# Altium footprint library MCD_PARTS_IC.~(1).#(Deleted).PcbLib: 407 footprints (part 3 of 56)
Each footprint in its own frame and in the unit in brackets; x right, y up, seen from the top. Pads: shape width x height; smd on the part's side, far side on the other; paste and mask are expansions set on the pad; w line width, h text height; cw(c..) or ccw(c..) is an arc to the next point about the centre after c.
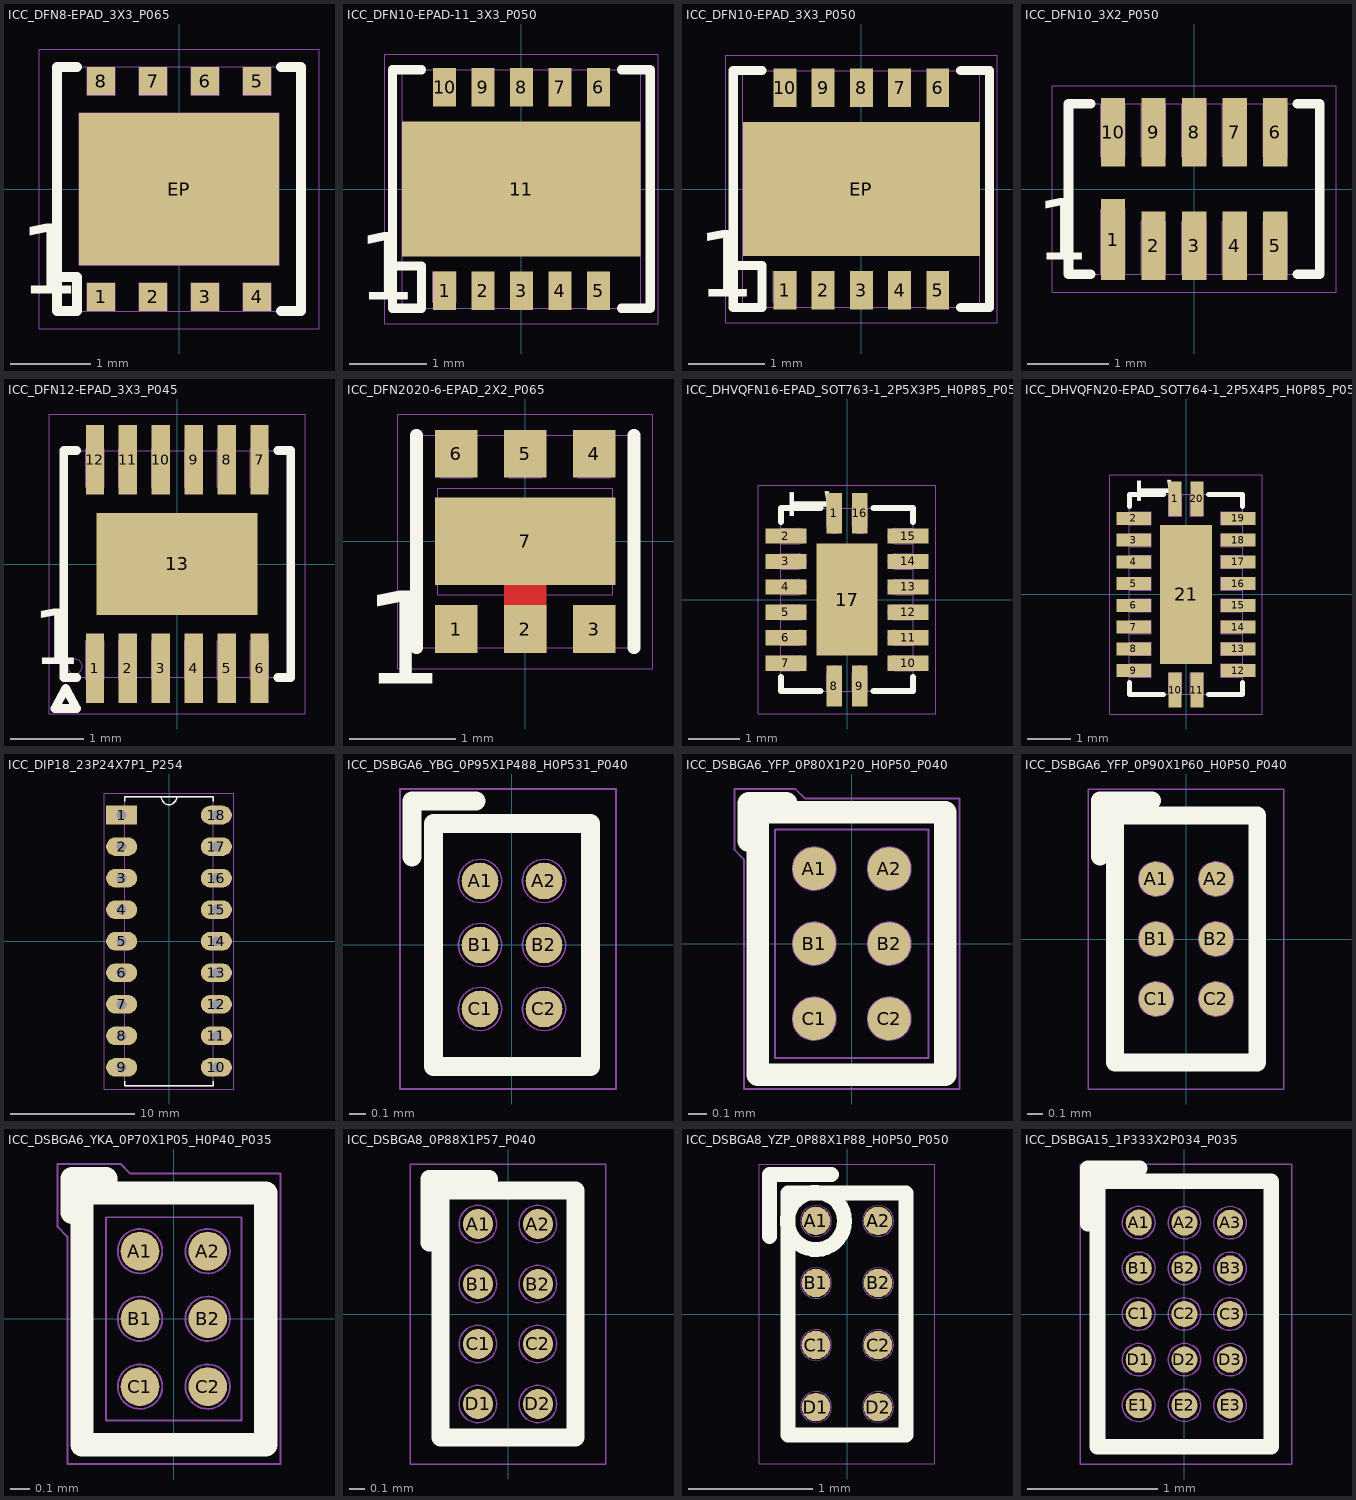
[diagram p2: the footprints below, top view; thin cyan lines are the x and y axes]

## ICC_DFN8-EPAD_3X3_P065 [mm]
height 0.9
pads (9):
  rect 0.35x0.35 smd mask+0.05: 1(-0.975,-1.35) 2(-0.325,-1.35) 3(0.325,-1.35) 4(0.975,-1.35) 5(0.975,1.35) 6(0.325,1.35) 7(-0.325,1.35) 8(-0.975,1.35)
  rect 2.5x1.9 smd mask+0.05: EP(0,0)
Top Overlay:
  lines w0.12: -1.525,-1.1 -1.275,-1.1 -1.275,-1.525 -1.525,-1.525 -1.525,1.525 -1.275,1.525 ; 1.275,-1.525 1.525,-1.525 1.525,1.525 1.275,1.525
  text "1" at -2,-1.6 h1.5
M14-Top Assembly:
  lines w0.01: -1.15,-1.525 -1.15,-1.175 -0.8,-1.175 -0.8,-1.525 ; -1.15,1.525 -1.15,1.175 -0.8,1.175 -0.8,1.525 ; -0.5,-1.525 -0.5,-1.175 -0.15,-1.175 -0.15,-1.525 ; -0.5,1.525 -0.5,1.175 -0.15,1.175 -0.15,1.525 ; 0.15,-1.525 0.15,-1.175 0.5,-1.175 0.5,-1.525 ; 0.15,1.525 0.15,1.175 0.5,1.175 0.5,1.525 ; 0.8,-1.525 0.8,-1.175 1.15,-1.175 1.15,-1.525 ; 0.8,1.525 0.8,1.175 1.15,1.175 1.15,1.525 ; -1.525,-1.525 1.525,-1.525 1.525,1.525 -1.525,1.525 -1.525,-1.525 ; -1.25,-0.95 1.25,-0.95 1.25,0.95 -1.25,0.95 -1.25,-0.95
  text "1" at -1.05,-1.525 h0.5
  text "4" at 0.85,-1.525 h0.5
  text "EP" at -0.25,-0.125 h0.5
  text "5" at 0.875,1.175 h0.5
  text "8" at -1.075,1.175 h0.5
  text "'.Designator'" at -2,0 h0.75
M16-Top Courtyard:
  lines w0.01: -1.75,-1.75 1.75,-1.75 1.75,1.75 -1.75,1.75 -1.75,-1.75
3D body: height 0.9, standoff 0, extent -1.525,-1.525 1.525,1.525
3D body "User Library-DFN8N_65.STEP": height 0.9, standoff 0, extent -1.49,-1.5 1.5,1.5

## ICC_DFN10-EPAD-11_3X3_P050 [mm]
height 1
pads (11):
  rect 0.3x0.5 smd mask+0.05: 1(-1,-1.325) 2(-0.5,-1.325) 3(0,-1.325) 4(0.5,-1.325) 5(1,-1.325) 6(1,1.325) 7(0.5,1.325) 8(0,1.325) 9(-0.5,1.325) 10(-1,1.325)
  rect 3.1x1.75 smd mask+0.05: 11(0,0)
Top Overlay:
  lines w0.12: -1.675,-1 -1.3,-1 -1.3,-1.55 -1.675,-1.55 -1.675,1.55 -1.3,1.55 ; 1.3,-1.55 1.675,-1.55 1.675,1.55 1.3,1.55
  text "1" at -2.125,-1.725 h1.5
M14-Top Assembly:
  lines w0.01: -1.55,-1.55 -1.55,1.55 1.55,1.55 1.55,-1.55 -1.55,-1.55 ; -1.15,-1.475 -0.85,-1.475 -0.85,-1.075 -1.15,-1.075 -1.15,-1.475
  text "'.Designator'" at -2,-0.5 h0.75
M16-Top Courtyard:
  lines w0.01: -1.775,-1.75 -1.775,1.75 1.775,1.75 1.775,-1.75 -1.775,-1.75
3D body "DFN-10-3x3-0_5.STEP": height 0.8, standoff 0, extent -1.55,-1.56 1.55,1.56
3D body: height 1, standoff 0, extent -1.55,-1.55 1.55,1.55

## ICC_DFN10-EPAD_3X3_P050 [mm]
height 1
pads (11):
  rect 0.3x0.5 smd mask+0.05: 1(-1,-1.325) 2(-0.5,-1.325) 3(0,-1.325) 4(0.5,-1.325) 5(1,-1.325) 6(1,1.325) 7(0.5,1.325) 8(0,1.325) 9(-0.5,1.325) 10(-1,1.325)
  rect 3.1x1.75 smd mask+0.05: EP(0,0)
Top Overlay:
  lines w0.12: -1.675,-1 -1.3,-1 -1.3,-1.55 -1.675,-1.55 -1.675,1.55 -1.3,1.55 ; 1.3,-1.55 1.675,-1.55 1.675,1.55 1.3,1.55
  text "1" at -2.15,-1.7 h1.5
M14-Top Assembly:
  lines w0.01: -1.55,-1.55 -1.55,1.55 1.55,1.55 1.55,-1.55 -1.55,-1.55 ; -1.15,-1.475 -0.85,-1.475 -0.85,-1.075 -1.15,-1.075 -1.15,-1.475
  text "'.Designator'" at -2,-0.5 h0.75
M16-Top Courtyard:
  lines w0.01: -1.775,-1.75 -1.775,1.75 1.775,1.75 1.775,-1.75 -1.775,-1.75
3D body "DFN-10-3x3-0_5.STEP": height 0.8, standoff 0, extent -1.55,-1.56 1.55,1.56
3D body: height 1, standoff 0, extent -1.55,-1.55 1.55,1.55

## ICC_DFN10_3X2_P050 [mm] "MCD-01488"
height 0.6
pads (10):
  rect 0.3x1 smd mask+0.05: 1(-1,-0.625)
  rect 0.3x0.85 smd mask+0.05: 2(-0.5,-0.7) 3(0,-0.7) 4(0.5,-0.7) 5(1,-0.7) 6(1,0.7) 7(0.5,0.7) 8(0,0.7) 9(-0.5,0.7) 10(-1,0.7)
Top Overlay:
  lines w0.12: -1.275,-1.05 -1.55,-1.05 -1.55,1.05 -1.275,1.05 ; 1.275,-1.05 1.55,-1.05 1.55,1.05 1.275,1.05
  text "1" at -1.95,-1.125 h1.3
M14-Top Assembly:
  lines w0.01: -1.15,-1.05 -1.15,-0.25 -0.85,-0.25 -0.85,-1.05 ; -1.15,1.05 -1.15,0.4 -0.85,0.4 -0.85,1.05 ; -0.65,-1.05 -0.65,-0.4 -0.35,-0.4 -0.35,-1.05 ; -0.65,1.05 -0.65,0.4 -0.35,0.4 -0.35,1.05 ; -0.15,-1.05 -0.15,-0.4 0.15,-0.4 0.15,-1.05 ; -0.15,1.05 -0.15,0.4 0.15,0.4 0.15,1.05 ; 0.35,-1.05 0.35,-0.4 0.65,-0.4 0.65,-1.05 ; 0.35,1.05 0.35,0.4 0.65,0.4 0.65,1.05 ; 0.85,-1.05 0.85,-0.4 1.15,-0.4 1.15,-1.05 ; 0.85,1.05 0.85,0.4 1.15,0.4 1.15,1.05 ; -1.55,-1.05 1.55,-1.05 1.55,1.05 -1.55,1.05 -1.55,-1.05
  text "10" at -1.3,0.55 h0.7
  text "6" at 0.85,0.55 h0.7
  text "5" at 0.85,-1 h0.7
  text "1" at -1.1,-1 h0.85
  text "'.Designator'" at -2,-0.5 h0.75
M16-Top Courtyard:
  lines w0.01: -1.75,-1.275 1.75,-1.275 1.75,1.275 -1.225,1.275 -1.75,1.275 -1.75,-1.25 -1.75,-1.275
3D body: height 0.6, standoff 0, extent -1.55,-1.05 1.55,1.05
3D body: height 0.61, standoff 0.6, extent -1.5,-1 -1.125,-0.625

## ICC_DFN12-EPAD_3X3_P045 [mm] "MCD-01952"
height 0.8
pads (13):
  rect 0.25x0.95 smd mask+0.05: 1(-1.125,-1.425) 2(-0.675,-1.425) 3(-0.225,-1.425) 4(0.225,-1.425) 5(0.675,-1.425) 6(1.125,-1.425) 7(1.125,1.425) 8(0.675,1.425) 9(0.225,1.425) 10(-0.225,1.425) 11(-0.675,1.425) 12(-1.125,1.425)
  rect 2.2x1.4 smd mask+0.05: 13(0,0)
Top Overlay:
  lines w0.12: -1.375,-1.55 -1.55,-1.55 ; 1.375,1.55 1.55,1.55 ; -1.55,-1.55 -1.55,1.55 -1.375,1.55 ; -1.55,-1.55 -1.55,-1.55 ; -1.375,1.55 -1.375,1.55 ; 1.375,-1.55 1.55,-1.55 1.55,1.55 ; 1.375,-1.55 1.375,-1.55 ; 1.55,1.55 1.55,1.55 ; -1.675,-1.975 -1.375,-1.975 -1.525,-1.7 -1.675,-1.975
  text "1" at -1.975,-1.625 h1.3
M14-Top Assembly:
  circle w0.01: c-1.4,-1.4 r0.1
  lines w0.01: -1.25,1.55 -1.25,1.575 ; -1,-1.55 -1,-1.575 ; -0.8,1.55 -0.8,1.575 ; -0.55,-1.55 -0.55,-1.575 ; -0.35,1.55 -0.35,1.575 ; -0.1,-1.55 -0.1,-1.575 ; 0.1,1.55 0.1,1.575 ; 0.35,-1.55 0.35,-1.575 ; 0.55,1.55 0.55,1.575 ; 0.8,-1.55 0.8,-1.575 ; 1,1.55 1,1.575 ; 1.25,-1.55 1.25,-1.575 ; -1.25,1.575 -1.25,1.05 -1,1.05 -1,1.55 -1,1.575 -1.25,1.575 ; -1.05,-0.45 -0.85,-0.65 1.05,-0.65 1.05,0.65 -1.05,0.65 -1.05,-0.45 ; -1.05,-0.45 -1.05,-0.45 ; -1,-1.575 -1.25,-1.575 -1.25,-1.55 -1.25,-1.05 -1,-1.05 -1,-1.575 ; -0.8,1.575 -0.55,1.575 -0.55,1.55 -0.55,1.05 -0.8,1.05 -0.8,1.575 ; -0.55,-1.575 -0.8,-1.575 -0.8,-1.55 -0.8,-1.05 -0.55,-1.05 -0.55,-1.575 ; -0.35,1.575 -0.1,1.575 -0.1,1.55 -0.1,1.05 -0.35,1.05 -0.35,1.575 ; -0.1,-1.575 -0.35,-1.575 -0.35,-1.55 -0.35,-1.05 -0.1,-1.05 -0.1,-1.575 ; 0.1,1.575 0.35,1.575 0.35,1.55 0.35,1.05 0.1,1.05 0.1,1.575 ; 0.35,-1.575 0.1,-1.575 0.1,-1.55 0.1,-1.05 0.35,-1.05 0.35,-1.575 ; 0.55,1.575 0.8,1.575 0.8,1.55 0.8,1.05 0.55,1.05 0.55,1.575 ; 0.8,-1.575 0.55,-1.575 0.55,-1.55 0.55,-1.05 0.8,-1.05 0.8,-1.575 ; 1,1.575 1.25,1.575 1.25,1.55 1.25,1.05 1,1.05 1,1.575 ; 1.25,-1.575 1,-1.575 1,-1.55 1,-1.05 1.25,-1.05 1.25,-1.575 ; -1.55,-1.55 1.55,-1.55 1.55,1.55 -1.55,1.55 -1.55,-1.55
  text "12" at -1.4,1.1 h0.6
  text "7" at 1,1.125 h0.6
  text "6" at 1,-1.5 h0.6
  text "1" at -1.2,-1.5 h0.6
  text "'.Designator'" at -2,0.125 h0.75
  text "13" at -0.275,-0.175 h0.6
M16-Top Courtyard:
  lines w0.01: -1.75,-2.05 1.75,-2.05 1.75,2.05 -1.75,2.05 -1.75,-2.05
3D body: height 0.8, standoff 0, extent -1.55,-1.55 1.55,1.55
3D body "DFN12(3x3)-1.STEP": height 0.76, standoff 0, extent -1.5,-1.501 1.5,1.501

## ICC_DFN2020-6-EPAD_2X2_P065 [mm] "MCD-012963"
height 0.65
pads (7):
  rect 0.4x0.45 smd mask+0.05: 1(-0.65,-0.825) 2(0,-0.825) 3(0.65,-0.825) 4(0.65,0.825) 5(0,0.825) 6(-0.65,0.825)
  rect 1.7x0.825 smd mask+0.05: 7(0,0)
Top Layer:
  region: -0.2,0.2 0.2,0.2 0.2,-1.05 -0.2,-1.05
Top Overlay:
  lines w0.12: -1.025,-1 -1.025,1 ; 1.025,-1 1.025,1
  text "1" at -1.525,-1.625 h1.5
M14-Top Assembly:
  lines w0.01: -0.8,-1 -0.8,-0.6 -0.5,-0.6 -0.5,-1 ; -0.8,1 -0.8,0.6 -0.5,0.6 -0.5,1 ; -0.15,-1 -0.15,-0.5 -0.825,-0.5 -0.825,0.5 0.825,0.5 0.825,-0.5 0.15,-0.5 0.15,-1 ; -0.15,1 -0.15,0.6 0.15,0.6 0.15,1 0.175,1 ; 0.475,1 0.5,1 0.5,0.6 0.8,0.6 0.8,1 0.825,1 ; 0.5,-1 0.5,-0.6 0.8,-0.6 0.8,-1 ; -1,-1 1,-1 1,1 -1,1 -1,-1
  text "'.Designator'" at 0,0 h0.75
  text "1" at -0.7,-0.975 h0.4
  text "2" at -0.075,-0.975 h0.4
  text "3" at 0.575,-0.975 h0.4
  text "4" at 0.55,0.725 h0.4
  text "5" at -0.075,0.725 h0.4
  text "6" at -0.725,0.725 h0.4
  text "7" at -0.075,-0.15 h0.4
M16-Top Courtyard:
  lines w0.01: -1.2,-1.2 -1.2,1.2 1.2,1.2 1.2,-1.2 -1.2,-1.2
3D body: height 1.01, standoff 1, extent -0.899,-0.9 -0.6,-0.6
3D body: height 0.6, standoff 0, extent -1,-1 1,1

## ICC_DHVQFN16-EPAD_SOT763-1_2P5X3P5_H0P85_P050 [mm] "MCD-01945"
height 1
pads (17):
  rect 0.3x0.8 smd mask+0.05: 1(-0.25,1.7) 8(-0.25,-1.7) 9(0.25,-1.7) 16(0.25,1.7)
  rect 0.8x0.3 smd mask+0.05: 2(-1.2,1.25) 3(-1.2,0.75) 4(-1.2,0.25) 5(-1.2,-0.25) 6(-1.2,-0.75) 7(-1.2,-1.25) 10(1.2,-1.25) 11(1.2,-0.75) 12(1.2,-0.25) 13(1.2,0.25) 14(1.2,0.75) 15(1.2,1.25)
  rect 1.2x2.2 smd mask+0.05: 17(0,0)
Top Overlay:
  lines w0.12: -1.3,-1.525 -1.3,-1.8 -0.525,-1.8 ; -1.3,1.525 -1.3,1.8 -0.525,1.8 ; 0.525,-1.8 1.3,-1.8 1.3,-1.525 ; 0.525,1.8 1.3,1.8 1.3,1.525
  text "1" at -1.4,2.25 h1.4
M14-Top Assembly:
  lines w0.01: -1.3,-1.4 -0.95,-1.4 ccw(c-0.95,-1.25) -0.8,-1.25 ccw(c-0.95,-1.25) -0.95,-1.1 -1.3,-1.1 ; -1.3,-0.9 -0.95,-0.9 ccw(c-0.95,-0.75) -0.8,-0.75 ccw(c-0.95,-0.75) -0.95,-0.6 -1.3,-0.6 ; -1.3,-0.4 -0.95,-0.4 ccw(c-0.95,-0.25) -0.8,-0.25 ccw(c-0.95,-0.25) -0.95,-0.1 -1.3,-0.1 ; -1.3,0.1 -0.95,0.1 ccw(c-0.95,0.25) -0.8,0.25 ccw(c-0.95,0.25) -0.95,0.4 -1.3,0.4 ; -1.3,0.6 -0.95,0.6 ccw(c-0.95,0.75) -0.8,0.75 ccw(c-0.95,0.75) -0.95,0.9 -1.3,0.9 ; -1.3,1.1 -0.95,1.1 ccw(c-0.95,1.25) -0.8,1.25 ccw(c-0.95,1.25) -0.95,1.4 -1.3,1.4 ; -0.4,-1.8 -0.4,-1.45 cw(c-0.25,-1.45) -0.25,-1.3 cw(c-0.25,-1.45) -0.1,-1.45 -0.1,-1.8 ; -0.4,1.8 -0.4,1.45 ccw(c-0.25,1.45) -0.25,1.3 ccw(c-0.25,1.45) -0.1,1.45 -0.1,1.8 ; 0.1,-1.8 0.1,-1.45 cw(c0.25,-1.45) 0.25,-1.3 cw(c0.25,-1.45) 0.4,-1.45 0.4,-1.8 ; 0.1,1.8 0.1,1.45 ccw(c0.25,1.45) 0.25,1.3 ccw(c0.25,1.45) 0.4,1.45 0.4,1.8 ; 1.3,-1.4 0.95,-1.4 cw(c0.95,-1.25) 0.8,-1.25 cw(c0.95,-1.25) 0.95,-1.1 1.3,-1.1 ; 1.3,-0.9 0.95,-0.9 cw(c0.95,-0.75) 0.8,-0.75 cw(c0.95,-0.75) 0.95,-0.6 1.3,-0.6 ; 1.3,-0.4 0.95,-0.4 cw(c0.95,-0.25) 0.8,-0.25 cw(c0.95,-0.25) 0.95,-0.1 1.3,-0.1 ; 1.3,0.1 0.95,0.1 cw(c0.95,0.25) 0.8,0.25 cw(c0.95,0.25) 0.95,0.4 1.3,0.4 ; 1.3,0.6 0.95,0.6 cw(c0.95,0.75) 0.8,0.75 cw(c0.95,0.75) 0.95,0.9 1.3,0.9 ; 1.3,1.1 0.95,1.1 cw(c0.95,1.25) 0.8,1.25 cw(c0.95,1.25) 0.95,1.4 1.3,1.4 ; -1.3,-1.8 1.3,-1.8 1.3,1.8 -1.3,1.8 -1.3,-1.8 ; -0.575,-1.075 0.575,-1.075 0.575,1.075 -0.575,1.075 -0.575,-1.075
  text "17" at -0.175,-0.125 h0.4
  text "16" at 0.425,1.7 h0.4
  text "2" at -1.175,1.325 h0.4
  text "7" at -1.2,-1.175 h0.4
  text "8" at -0.325,-1.675 h0.4
  text "9" at 0.175,-1.675 h0.4
  text "10" at 1.225,-1.425 h0.4
  text "15" at 1.225,1.075 h0.4
  text "'.Designator'" at -2,-0.5 h0.75
  text "1" at -0.2,1.7 h0.4
M16-Top Courtyard:
  lines w0.01: -1.75,-2.25 1.75,-2.25 1.75,2.25 -1.75,2.25 -1.75,-2.25
3D body "User Library-User Library-DHVQFN 16-1.STEP": height 1, standoff -0.05, extent -1.31,-1.81 1.31,1.81
3D body: height 1, standoff 0, extent -1.3,-1.81 1.3,1.81
3D body: height 1.01, standoff 1, extent -0.624,1.326 -0.226,1.725

## ICC_DHVQFN20-EPAD_SOT764-1_2P5X4P5_H0P85_P050 [mm] "MCD-01620"
height 1
pads (21):
  rect 0.3x0.8 smd mask+0.05: 1(-0.25,2.2) 10(-0.25,-2.2) 11(0.25,-2.2) 20(0.25,2.2)
  rect 0.8x0.3 smd mask+0.05: 2(-1.2,1.75) 3(-1.2,1.25) 4(-1.2,0.75) 5(-1.2,0.25) 6(-1.2,-0.25) 7(-1.2,-0.75) 8(-1.2,-1.25) 9(-1.2,-1.75) 12(1.2,-1.75) 13(1.2,-1.25) 14(1.2,-0.75) 15(1.2,-0.25) 16(1.2,0.25) 17(1.2,0.75) 18(1.2,1.25) 19(1.2,1.75)
  rect 1.2x3.2 smd mask+0.05: 21(0,0)
Top Overlay:
  lines w0.12: -1.3,-2.025 -1.3,-2.3 -0.525,-2.3 ; -1.3,2.025 -1.3,2.3 -0.525,2.3 ; 0.525,-2.3 1.3,-2.3 1.3,-2.025 ; 0.525,2.3 1.3,2.3 1.3,2.025
  text "1" at -1.4,2.75 h1.4
M14-Top Assembly:
  lines w0.01: -1.3,-1.9 -0.8,-1.9 -0.8,-1.6 -1.3,-1.6 ; -1.3,-1.4 -0.8,-1.4 -0.8,-1.1 -1.3,-1.1 ; -1.3,-0.9 -0.8,-0.9 -0.8,-0.6 -1.3,-0.6 ; -1.3,-0.4 -0.8,-0.4 -0.8,-0.1 -1.3,-0.1 ; -1.3,0.1 -0.8,0.1 -0.8,0.4 -1.3,0.4 ; -1.3,0.6 -0.8,0.6 -0.8,0.9 -1.3,0.9 ; -1.3,1.1 -0.8,1.1 -0.8,1.4 -1.3,1.4 ; -1.3,1.6 -0.8,1.6 -0.8,1.9 -1.3,1.9 ; -0.4,-2.3 -0.4,-1.8 -0.1,-1.8 -0.1,-2.3 ; -0.4,2.3 -0.4,1.8 -0.1,1.8 -0.1,2.3 ; 0.1,-2.3 0.1,-1.8 0.4,-1.8 0.4,-2.3 ; 0.1,2.3 0.1,1.8 0.4,1.8 0.4,2.3 ; 1.3,-1.9 0.8,-1.9 0.8,-1.6 1.3,-1.6 ; 1.3,-1.4 0.8,-1.4 0.8,-1.1 1.3,-1.1 ; 1.3,-0.9 0.8,-0.9 0.8,-0.6 1.3,-0.6 ; 1.3,-0.4 0.8,-0.4 0.8,-0.1 1.3,-0.1 ; 1.3,0.1 0.8,0.1 0.8,0.4 1.3,0.4 ; 1.3,0.6 0.8,0.6 0.8,0.9 1.3,0.9 ; 1.3,1.1 0.8,1.1 0.8,1.4 1.3,1.4 ; 1.3,1.6 0.8,1.6 0.8,1.9 1.3,1.9 ; -1.3,-2.3 1.3,-2.3 1.3,2.3 -1.3,2.3 -1.3,-2.3 ; -0.575,-1.575 0.575,-1.575 0.575,1.575 -0.575,1.575 -0.575,-1.575
  text "1" at -0.3,1.95 h0.35
  text "'.Designator'" at -2,0.3 h0.75
  text "20" at 0.1,1.95 h0.35
  text "2" at -1.1,1.65 h0.35
  text "9" at -1.1,-1.875 h0.35
  text "10" at -0.4,-2.175 h0.35
  text "11" at 0.125,-2.175 h0.35
  text "21" at -0.15,-0.125 h0.35
  text "12" at 0.9,-1.875 h0.35
  text "19" at 0.9,1.65 h0.35
M16-Top Courtyard:
  lines w0.01: -1.75,-2.75 -1.75,2.75 -1.3,2.75 1.75,2.75 1.75,2.55 1.75,-2.75 -0.4,-2.75 -1.75,-2.75
3D body "DHVQFN20.STEP": height 1, standoff 0, extent -1.26,-2.26 1.26,2.26
3D body: height 1, standoff 0, extent -1.3,-2.3 1.3,2.3
3D body: height 1.01, standoff 1, extent -0.648,1.8 -0.25,2.2
3D body: height 1.01, standoff 1, extent -0.648,1.801 -0.25,2.2

## ICC_DIP18_23P24X7P1_P254 [mm] "MCD-03104"
height 3.93
pads (18):
  rect 2.5x1.5 hole 0.8 mask+0.05: 1(-3.81,10.16)
  oval 2.5x1.5 hole 0.8 mask+0.05: 2(-3.81,7.62) 3(-3.81,5.08) 4(-3.81,2.54) 5(-3.81,0) 6(-3.81,-2.54) 7(-3.81,-5.08) 8(-3.81,-7.62) 9(-3.81,-10.16) 10(3.81,-10.16) 11(3.81,-7.62) 12(3.81,-5.08) 13(3.81,-2.54) 14(3.81,0) 15(3.81,2.54) 16(3.81,5.08) 17(3.81,7.62) 18(3.81,10.16)
Top Overlay:
  lines w0.12: -3.55,-11.261 -3.55,-11.62 3.55,-11.62 3.55,-11.261 ; -3.55,11.261 -3.55,11.62 3.55,11.62 3.55,11.261 ; -0.624,11.62 ccw(c-0.004,11.62) -0.004,11 ccw(c-0.004,11.629) 0.625,11.62
M14-Top Assembly:
  lines w0.01: -0.624,11.62 ccw(c-0.004,11.62) -0.004,11 ccw(c-0.004,11.629) 0.625,11.62 ; -3.55,-11.62 3.55,-11.62 3.55,11.62 -3.55,11.62 -3.55,-11.62
  text "1" at -3.925,9.9 h1
  text "'.Designator'" at -2,-0.5 h0.75
M16-Top Courtyard:
  lines w0.01: -5.2,-11.9 5.2,-11.9 5.2,11.9 -5.2,11.9 -5.2,-11.9
3D body "User Library-DIP-18P-M02.STEP": height 5, standoff -3, extent -3.945,-11 3.925,11

## ICC_DSBGA6_YBG_0P95X1P488_H0P531_P040 [mm] "MCD-04417"
height 0.531
pads (6):
  round 0.23 smd paste+0 mask+0.05: A1(-0.2,0.4) A2(0.2,0.4) B1(-0.2,0) B2(0.2,0) C1(-0.2,-0.4) C2(0.2,-0.4)
Top Overlay:
  lines w0.12: -0.625,0.55 -0.625,0.9 -0.225,0.9 ; -0.49,-0.759 -0.49,0.759 0.49,0.759 0.49,-0.759 -0.49,-0.759
Top Paste:
  drawing of 6 lines, arcs and shapes, not listed
M14-Top Assembly:
  circle w0.01: c-0.2,0.4 r0.135
  circle w0.01: c0.2,0.4 r0.135
  circle w0.01: c-0.2,0 r0.135
  circle w0.01: c0.2,0 r0.135
  circle w0.01: c0.2,-0.4 r0.135
  circle w0.01: c-0.2,-0.4 r0.135
  lines w0.01: -0.475,0.759 -0.49,0.759 ; -0.49,0.759 0.49,0.759 0.49,-0.759 -0.49,-0.759 -0.49,0.759
  text "A1" at -0.317,0.323 h0.25
  text "A2" at 0.069,0.323 h0.25
  text "B1" at -0.308,-0.077 h0.25
  text "B2" at 0.077,-0.077 h0.25
  text "C1" at -0.317,-0.479 h0.25
  text "C2" at 0.068,-0.479 h0.25
  text ".Designator" at -2.252,-0.226 h1
M16-Top Courtyard:
  lines w0.01: -0.7,-0.9 0.65,-0.9 0.65,0.975 -0.7,0.975 -0.7,-0.9
3D body: height 0.27, standoff 0, extent 0.061,-0.535 0.331,-0.265
3D body: height 0.27, standoff 0, extent -0.339,-0.535 -0.069,-0.265
3D body: height 0.27, standoff 0, extent 0.061,-0.135 0.331,0.135
3D body: height 0.27, standoff 0, extent -0.339,-0.135 -0.069,0.135
3D body: height 0.27, standoff 0, extent 0.061,0.265 0.331,0.535
3D body: height 0.27, standoff 0, extent -0.339,0.265 -0.069,0.535
3D body: height 0.53, standoff 0.53, extent -0.49,0.449 -0.28,0.759
3D body: height 0.53, standoff 0.16, extent -0.49,-0.759 0.49,0.759

## ICC_DSBGA6_YFP_0P80X1P20_H0P50_P040 [mm] "MCD-02469"
height 0.5
pads (6):
  round 0.23 smd paste+0 mask+0.05: A1(-0.2,0.4) A2(0.2,0.4) B1(-0.2,0) B2(0.2,0) C1(-0.2,-0.4) C2(0.2,-0.4)
Top Overlay:
  lines w0.12: -0.55,0.55 -0.55,0.75 -0.35,0.75 ; -0.35,0.7 -0.5,0.7 ; -0.5,0.7 0.5,0.7 0.5,-0.7 -0.5,-0.7 -0.5,0.7
Top Paste:
  drawing of 6 lines, arcs and shapes, not listed
M14-Top Assembly:
  circle w0.01: c-0.2,0.4 r0.115
  circle w0.01: c0.2,0.4 r0.115
  circle w0.01: c-0.2,0 r0.115
  circle w0.01: c0.2,0 r0.115
  circle w0.01: c0.2,-0.4 r0.115
  circle w0.01: c-0.2,-0.4 r0.115
  lines w0.01: -0.41,-0.61 0.41,-0.61 0.41,0.61 -0.41,0.61 -0.41,-0.61
  text "'.Designator'" at -2,-0.5 h0.75
  text "A1" at -0.317,0.323 h0.25
  text "A2" at 0.069,0.323 h0.25
  text "B1" at -0.308,-0.077 h0.25
  text "B2" at 0.077,-0.077 h0.25
  text "C1" at -0.317,-0.479 h0.25
  text "C2" at 0.068,-0.479 h0.25
M16-Top Courtyard:
  lines w0.01: -0.625,0.5 -0.625,0.825 -0.3,0.825 -0.25,0.775 0.575,0.775 0.575,-0.775 -0.575,-0.775 -0.575,0.45 -0.625,0.5
3D body: height 0.5, standoff 0.16, extent -0.41,-0.61 0.41,0.61
3D body: height 0.24, standoff -0.02, extent 0.074,-0.528 0.326,-0.272
3D body: height 0.24, standoff -0.02, extent -0.326,-0.528 -0.074,-0.272
3D body: height 0.24, standoff -0.02, extent 0.074,-0.128 0.326,0.128
3D body: height 0.24, standoff -0.02, extent -0.326,-0.128 -0.074,0.128
3D body: height 0.24, standoff -0.02, extent 0.074,0.272 0.326,0.528
3D body: height 0.24, standoff -0.02, extent -0.326,0.272 -0.074,0.528
3D body: height 0.51, standoff 0.5, extent -0.41,0.3 -0.2,0.61

## ICC_DSBGA6_YFP_0P90X1P60_H0P50_P040 [mm] "MCD-03759"
height 0.5
pads (6):
  round 0.23 smd paste+0 mask+0.05: A1(-0.2,0.4) A2(0.2,0.4) B1(-0.2,0) B2(0.2,0) C1(-0.2,-0.4) C2(0.2,-0.4)
Top Overlay:
  lines w0.12: -0.575,0.55 -0.575,0.925 -0.225,0.925 ; -0.475,-0.825 0.475,-0.825 0.475,0.825 -0.475,0.825 -0.475,-0.825
Top Paste:
  drawing of 6 lines, arcs and shapes, not listed
M14-Top Assembly:
  circle w0.01: c-0.2,-0.4 r0.115
  circle w0.01: c0.2,-0.4 r0.115
  circle w0.01: c0.2,0 r0.115
  circle w0.01: c-0.2,0 r0.115
  circle w0.01: c0.2,0.4 r0.115
  circle w0.01: c-0.2,0.4 r0.115
  lines w0.01: -0.45,-0.8 0.45,-0.8 0.45,0.8 -0.45,0.8 -0.45,-0.8
  text ".Designator" at -2.252,-0.226 h1
  text "C2" at 0.068,-0.479 h0.25
  text "C1" at -0.317,-0.479 h0.25
  text "B2" at 0.077,-0.077 h0.25
  text "B1" at -0.308,-0.077 h0.25
  text "A2" at 0.069,0.323 h0.25
  text "A1" at -0.317,0.323 h0.25
M16-Top Courtyard:
  lines w0.01: -0.65,-1 0.65,-1 0.65,1 -0.65,1 -0.65,-1
3D body: height 0.5, standoff 0.16, extent -0.45,-0.8 0.45,0.8
3D body: height 0.51, standoff 0.5, extent -0.43,0.47 -0.22,0.78
3D body: height 0.24, standoff -0.02, extent -0.326,0.272 -0.074,0.528
3D body: height 0.24, standoff -0.02, extent 0.074,0.272 0.326,0.528
3D body: height 0.24, standoff -0.02, extent -0.326,-0.128 -0.074,0.128
3D body: height 0.24, standoff -0.02, extent 0.074,-0.128 0.326,0.128
3D body: height 0.24, standoff -0.02, extent -0.326,-0.528 -0.074,-0.272
3D body: height 0.24, standoff -0.02, extent 0.074,-0.528 0.326,-0.272

## ICC_DSBGA6_YKA_0P70X1P05_H0P40_P035 [mm] "MCD-03717"
height 0.4
pads (6):
  round 0.2 smd paste+0 mask+0.032: A1(-0.175,0.35) A2(0.175,0.35) B1(-0.175,0) B2(0.175,0) C1(-0.175,-0.35) C2(0.175,-0.35)
Top Overlay:
  lines w0.12: -0.525,0.55 -0.525,0.725 -0.35,0.725 ; -0.5,0.7 -0.45,0.65 0.475,0.65 0.475,-0.65 -0.475,-0.65 -0.475,0.7 -0.35,0.7
Top Paste:
  drawing of 6 lines, arcs and shapes, not listed
M14-Top Assembly:
  circle w0.01: c-0.175,-0.35 r0.115
  circle w0.01: c0.175,-0.35 r0.115
  circle w0.01: c0.175,0 r0.115
  circle w0.01: c-0.175,0 r0.115
  circle w0.01: c0.175,0.35 r0.115
  circle w0.01: c-0.175,0.35 r0.115
  lines w0.01: -0.35,-0.525 -0.35,0.525 0.35,0.525 0.35,-0.525 -0.35,-0.525
  text "C2" at 0.068,-0.429 h0.25
  text "C1" at -0.317,-0.429 h0.25
  text "B2" at 0.077,-0.077 h0.25
  text "B1" at -0.308,-0.077 h0.25
  text "A2" at 0.069,0.273 h0.25
  text "A1" at -0.317,0.273 h0.25
  text "'.Designator'" at -2,-0.5 h0.75
M16-Top Courtyard:
  lines w0.01: -0.6,0.475 -0.55,0.425 -0.55,-0.75 0.55,-0.75 0.55,0.75 -0.225,0.75 -0.275,0.8 -0.6,0.8 -0.6,0.475
3D body: height 0.41, standoff 0.31, extent -0.35,0.215 -0.14,0.525
3D body: height 0.24, standoff -0.02, extent -0.297,0.222 -0.045,0.478
3D body: height 0.24, standoff -0.02, extent 0.053,0.222 0.305,0.478
3D body: height 0.24, standoff -0.02, extent -0.297,-0.128 -0.045,0.128
3D body: height 0.24, standoff -0.02, extent 0.053,-0.128 0.305,0.128
3D body: height 0.24, standoff -0.02, extent -0.297,-0.478 -0.045,-0.222
3D body: height 0.24, standoff -0.02, extent 0.053,-0.478 0.305,-0.222
3D body: height 0.4, standoff 0.16, extent -0.35,-0.525 0.35,0.525

## ICC_DSBGA8_0P88X1P57_P040 [mm]
height 0.5
pads (8):
  round 0.2 smd mask+0.05: A1(-0.2,0.6) A2(0.2,0.6) B1(-0.2,0.2) B2(0.2,0.2) C1(-0.2,-0.2) C2(0.2,-0.2) D1(-0.2,-0.6) D2(0.2,-0.6)
Top Overlay:
  lines w0.12: -0.525,0.475 -0.525,0.9 -0.125,0.9 ; -0.45,-0.825 0.45,-0.825 0.45,0.825 -0.45,0.825 -0.45,-0.8 -0.45,-0.825
M14-Top Assembly:
  circle w0.01: c-0.2,0.6 r0.125
  circle w0.01: c0.2,0.6 r0.125
  circle w0.01: c0.2,0.2 r0.125
  circle w0.01: c0.2,-0.2 r0.125
  circle w0.01: c0.2,-0.6 r0.125
  circle w0.01: c-0.2,-0.6 r0.125
  circle w0.01: c-0.2,-0.2 r0.125
  circle w0.01: c-0.2,0.2 r0.125
  lines w0.01: -0.45,-0.8 -0.45,0.8 0.45,0.8 0.45,-0.8 -0.45,-0.8
  text "A1" at -0.325,0.525 h0.25
  text "B1" at -0.3,0.125 h0.25
  text "C1" at -0.325,-0.275 h0.25
  text "D1" at -0.325,-0.675 h0.25
  text "D2" at 0.1,-0.675 h0.25
  text "C2" at 0.075,-0.275 h0.25
  text "B2" at 0.1,0.125 h0.25
  text "A2" at 0.075,0.525 h0.25
  text "'.Designator'" at -2,-0.5 h0.75
M16-Top Courtyard:
  lines w0.01: -0.65,-1 0.65,-1 0.65,0.725 0.65,1 -0.65,1 -0.65,-1
3D body: height 0.5, standoff 0, extent -0.45,-0.8 0.45,0.8
3D body: height 0.51, standoff 0.5, extent -0.319,0.48 -0.08,0.72

## ICC_DSBGA8_YZP_0P88X1P88_H0P50_P050 [mm] "MCD-01624"
height 0.5
pads (8):
  round 0.23 smd mask+0.05: A1(-0.25,0.75) A2(0.25,0.75) B1(-0.25,0.25) B2(0.25,0.25) C1(-0.25,-0.25) C2(0.25,-0.25) D1(-0.25,-0.75) D2(0.25,-0.75)
Top Overlay:
  circle w0.12: c-0.25,0.75 r0.23
  lines w0.12: -0.625,0.625 -0.625,1.1 -0.625,1.125 -0.125,1.125 ; -0.475,-0.975 0.475,-0.975 0.475,0.975 -0.475,0.975 -0.475,-0.975
M14-Top Assembly:
  circle w0.01: c-0.25,-0.75 r0.125
  circle w0.01: c0.25,-0.25 r0.125
  circle w0.01: c-0.25,-0.25 r0.125
  circle w0.01: c0.25,0.25 r0.125
  circle w0.01: c-0.25,0.25 r0.125
  circle w0.01: c0.25,0.75 r0.125
  circle w0.01: c-0.25,0.75 r0.125
  circle w0.01: c0.25,-0.75 r0.125
  lines w0.01: -0.459,-0.959 0.459,-0.959 0.459,0.959 0,0.959 -0.459,0.959 -0.459,-0.959
  text "D2" at 0.15,-0.813 h0.2
  text "C2" at 0.138,-0.312 h0.2
  text "B2" at 0.15,0.188 h0.2
  text "A2" at 0.15,0.687 h0.2
  text "D1" at -0.35,-0.813 h0.2
  text "C1" at -0.35,-0.312 h0.2
  text "B1" at -0.337,0.188 h0.2
  text "A1" at -0.35,0.687 h0.2
  text "'.Designator'" at -2,-0.5 h0.75
M16-Top Courtyard:
  lines w0.01: -0.709,-1.209 0.709,-1.209 0.709,1.209 -0.709,1.209 -0.709,-1.209
3D body: height 0.5, standoff 0, extent -0.459,-0.959 0.459,0.959
3D body "DSBGA8_YZP.STEP": height 0.63, standoff 0, extent -0.45,-0.95 0.45,0.95

## ICC_DSBGA15_1P333X2P034_P035 [mm] "MCD-03403"
height 0.5
pads (15):
  round 0.2 smd mask+0.038: A1(-0.35,0.7) A2(0,0.7) A3(0.35,0.7) B1(-0.35,0.35) B2(0,0.35) B3(0.35,0.35) C1(-0.35,0) C2(0,0) C3(0.35,0) D1(-0.35,-0.35) D2(0,-0.35) D3(0.35,-0.35) E1(-0.35,-0.7) E2(0,-0.7) E3(0.35,-0.7)
Top Overlay:
  lines w0.12: -0.742,0.692 -0.742,1.117 -0.342,1.117 ; -0.667,-1.017 0.667,-1.017 0.667,1.017 -0.667,1.017 -0.667,-1.017
M14-Top Assembly:
  circle w0.01: c0,0 r0.125
  circle w0.01: c-0.35,0 r0.125
  circle w0.01: c0.35,0 r0.125
  circle w0.01: c0,0.35 r0.125
  circle w0.01: c-0.35,0.35 r0.125
  circle w0.01: c0.35,0.35 r0.125
  circle w0.01: c0,0.7 r0.125
  circle w0.01: c-0.35,0.7 r0.125
  circle w0.01: c0.35,0.7 r0.125
  circle w0.01: c0,-0.7 r0.125
  circle w0.01: c-0.35,-0.7 r0.125
  circle w0.01: c0.35,-0.7 r0.125
  circle w0.01: c0,-0.35 r0.125
  circle w0.01: c-0.35,-0.35 r0.125
  circle w0.01: c0.35,-0.35 r0.125
  lines w0.01: -0.667,-1.017 -0.667,1.017 0.667,1.017 0.667,-1.017 -0.667,-1.017
  text "'.Designator'" at -2,-0.5 h0.75
  text "A1" at -0.6,0.6 h0.4
M16-Top Courtyard:
  lines w0.01: -0.8,-1.15 0.825,-1.15 0.825,1.15 -0.8,1.15 -0.8,-1.15
3D body: height 0.19, standoff -0.01, extent -0.444,-0.798 -0.25,-0.601
3D body: height 0.19, standoff -0.01, extent -0.094,-0.798 0.1,-0.601
3D body: height 0.19, standoff -0.01, extent 0.256,-0.799 0.45,-0.602
3D body: height 0.19, standoff -0.01, extent 0.256,-0.449 0.45,-0.252
3D body: height 0.19, standoff -0.01, extent -0.094,-0.448 0.1,-0.251
3D body: height 0.19, standoff -0.01, extent -0.444,-0.448 -0.25,-0.251
3D body: height 0.19, standoff -0.01, extent -0.444,-0.098 -0.25,0.099
3D body: height 0.19, standoff -0.01, extent -0.094,-0.098 0.1,0.099
3D body: height 0.19, standoff -0.01, extent 0.256,-0.098 0.45,0.099
3D body: height 0.19, standoff -0.01, extent 0.256,0.252 0.45,0.449
3D body: height 0.19, standoff -0.01, extent -0.094,0.252 0.1,0.449
3D body: height 0.19, standoff -0.01, extent -0.444,0.252 -0.25,0.449
3D body: height 0.19, standoff -0.01, extent -0.444,0.602 -0.25,0.799
3D body: height 0.19, standoff -0.01, extent -0.094,0.602 0.1,0.799
3D body: height 0.5, standoff 0.16, extent -0.667,-1.017 0.667,1.017
3D body: height 0.51, standoff 0.5, extent -0.564,0.686 -0.325,0.925
3D body: height 0.19, standoff -0.01, extent 0.253,0.601 0.447,0.798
